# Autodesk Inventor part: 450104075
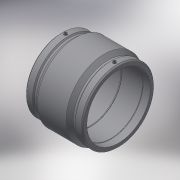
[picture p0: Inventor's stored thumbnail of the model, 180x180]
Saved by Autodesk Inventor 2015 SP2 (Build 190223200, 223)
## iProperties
Created: 2017-06
Part Number: 450104075
Material: Generic
Description: PLASSON COUPLER 75 PN25
Document SubType Name: Modeling
Designer: KIM
Mass: 8622.19 g
Surface Area: 6772.47 cm^2
Volume: 8622.19 cm^3
Density: 1 g/cm^3
Appearance: Default
Author: KIM
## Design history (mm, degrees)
derived "450104.ipt"
feature "Solid1::450104.ipt"
tag "TaggingFeature1"
body "Solid1"
other parameters: "d0" = 126, "d1" = 75, "d2" = 97, "d3" = 62, "d4" = 31.5, "d5" = 87.3, "d7" = 75, "d8" = 168 deg, "d10" = 24.8, "d11" = 8.26667, "d13" = 126, "d14" = 17.6296, "d15" = 62, "d16" = 62, "d17" = 74.25, "d18" = 75, "d19" = 3.52592, "d20" = 168 deg, "d22" = 91.18, "d23" = 97, "d24" = 88.4446, "d25" = 135 deg, "d26" = 56.7, "d27" = 135 deg, "d29" = 65, "d30" = 15, "d31" = 44.1, "d34" = 5 deg, "d35" = 15, "d39" = 5 deg, "d41" = 4, "d42" = 14, "d43" = 0, "d45" = 4, "d46" = 14, "d47" = 0, "d48" = 3, "d49" = 0, "d50" = 3, "d51" = 0, "d52" = 17.98, "d53" = 4.495, "d_" = 75, "L_" = 126, "L_1" = 62, "D_" = 97, "A_" = 65, "d_2" = 12
